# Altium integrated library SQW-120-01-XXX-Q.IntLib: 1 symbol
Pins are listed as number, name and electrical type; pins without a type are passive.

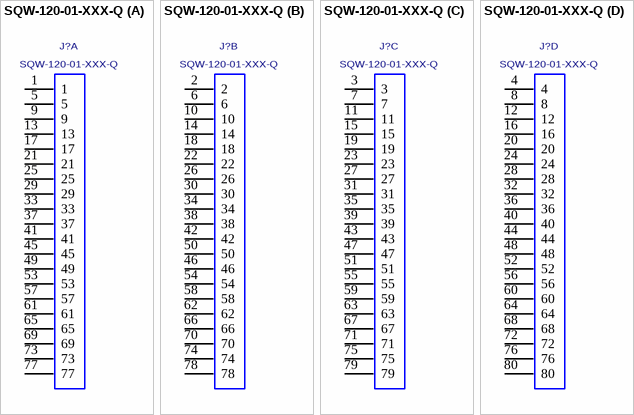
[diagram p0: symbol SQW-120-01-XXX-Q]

## SQW-120-01-XXX-Q
designator J?
2MM QUAD ROW FULL SHROUD TERMINAL ASM.; MANUFACTURER: SAMTEC
footprint SQW-120-01-XXX-Q
part A pins: 1, 5, 9, 13, 17, 21, 25, 29, 33, 37, 41, 45, 49, 53, 57, 61, 65, 69, 73, 77
part B pins: 2, 6, 10, 14, 18, 22, 26, 30, 34, 38, 42, 46, 50, 54, 58, 62, 66, 70, 74, 78
part C pins: 3, 7, 11, 15, 19, 23, 27, 31, 35, 39, 43, 47, 51, 55, 59, 63, 67, 71, 75, 79
part D pins: 4, 8, 12, 16, 20, 24, 28, 32, 36, 40, 44, 48, 52, 56, 60, 64, 68, 72, 76, 80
